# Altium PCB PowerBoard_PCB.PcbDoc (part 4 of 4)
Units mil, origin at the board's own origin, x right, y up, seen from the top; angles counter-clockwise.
Board outline 9251.97 x 3346.46 mil, 6 copper layers (Top Layer, Signal Layer 1, Signal Layer 2, Signal Layer 3, Signal Layer 4, Bottom Layer), stack 65.8 mil thick; 241 components, 145 nets, 894 pads, 120 vias.
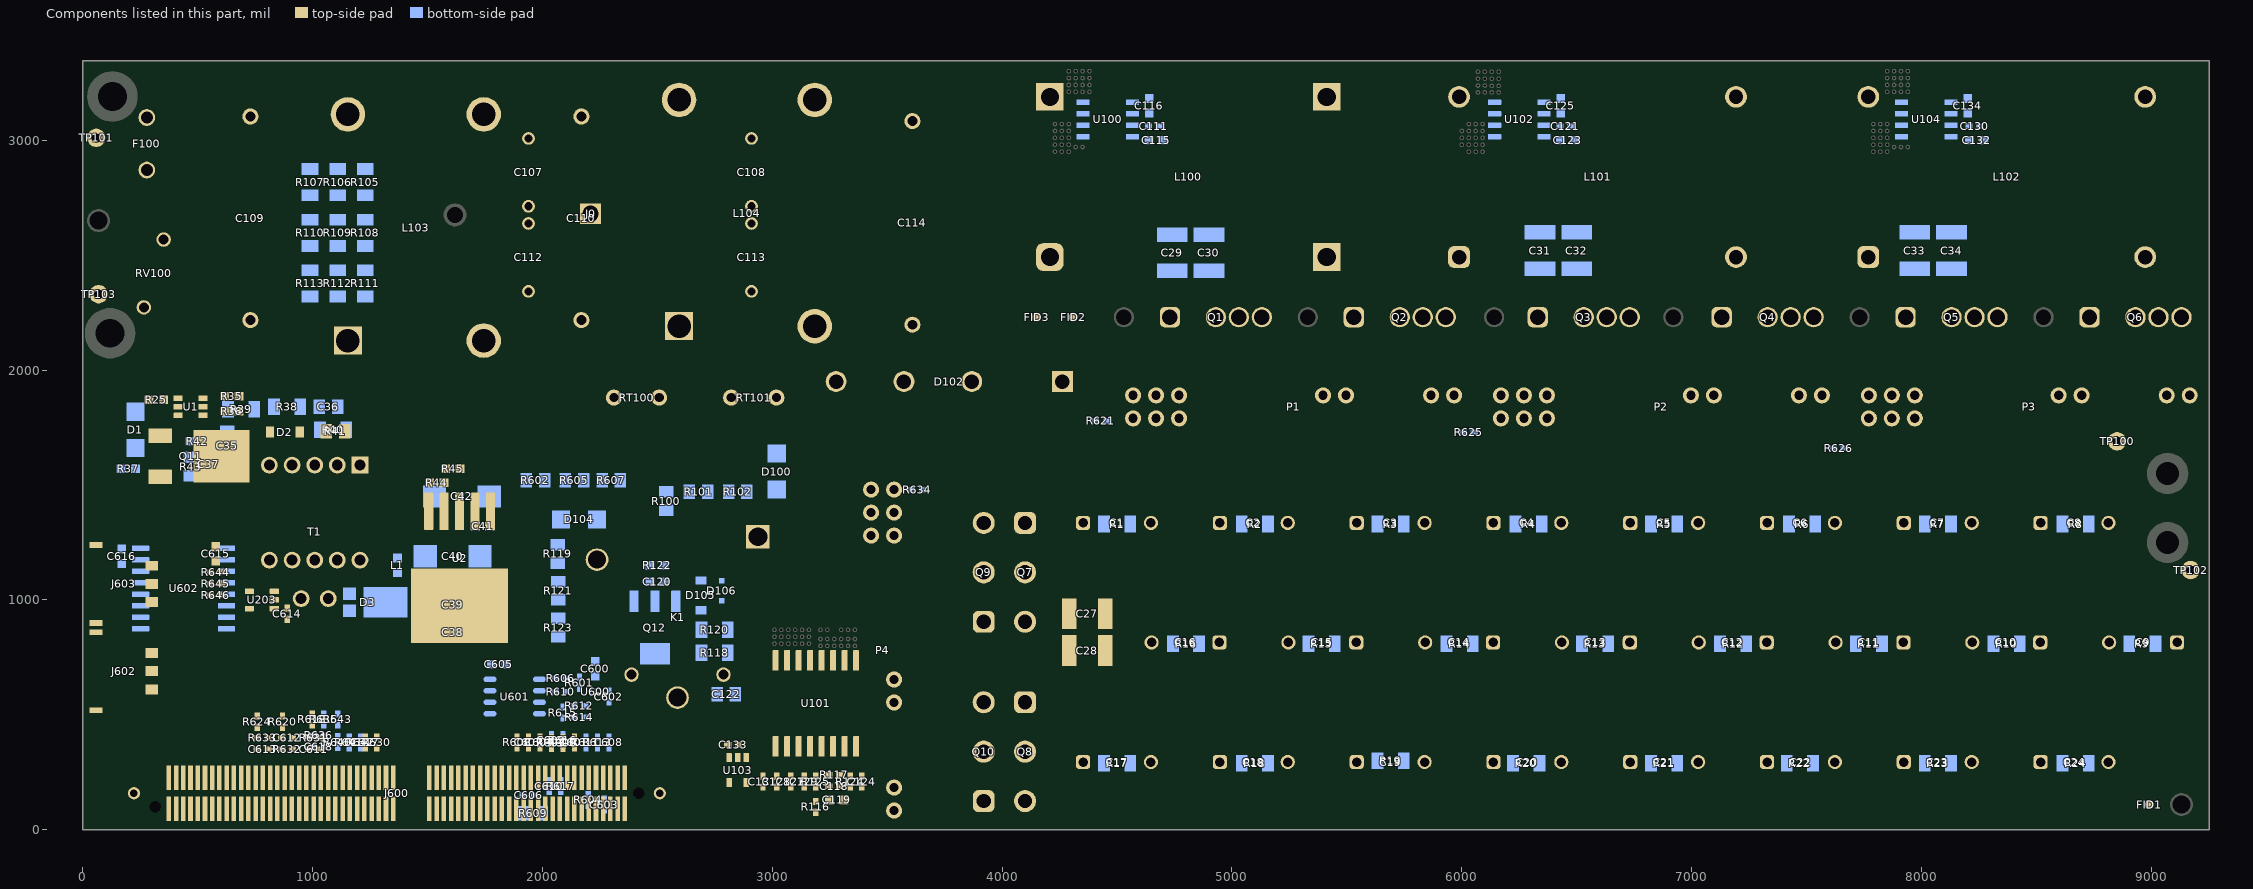
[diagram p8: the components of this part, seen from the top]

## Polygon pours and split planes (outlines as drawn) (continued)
NetC107_1 on Signal Layer 3 "Top Layer-No Net" (solid, pour order 398): 1580,3270 1630,3320 2700,3320 2750,3270 2750,3040 2700,2990 1630,2990 1580,3040
no net on Signal Layer 1 "Signal Layer 1-No Net 2" (solid, pour order 366): 3860,1170 3890,1200 4169.03,1200 4230,1260.97 4259.03,1260.97 4260,1260 4260,980 4230,980 4170,1040 3890,1040 3860,1070
NetC113_2 on Signal Layer 1 "Top Layer-No Net 8" (solid, remove dead copper, pour order 348): 3280,2300 3310,2270 3310,2250 3310,1250 3280,1220 2820,1220 2790,1250 2790,2260 2830,2300
AC_N on Signal Layer 1 "Signal Layer 1-No Net 5" (solid, pour order 342): 2170,1620 2490.13,1930.13 2855.07,1930.13 2871.7,1913.5 2871.7,1846.5 2855.07,1829.87 2656.06,1830 2630,1800 2620,1790 2620,1340 2780,1210 2170,1210
PFC_4H_S on Signal Layer 1 "Signal Layer 1-No Net 4" (solid, remove dead copper, pour order 340): 18 vertices, not listed, extent 3500,1399.92 4040,2000
AC_L on Signal Layer 1 "Signal Layer 1-No Net 3" (solid, remove dead copper, pour order 338): 3810,1900 3790,1920 3790,2040 3790,2890 4070,2890 4070,2090 4020,2030 4020,1920 4000,1900
NetL102_4 on Signal Layer 1 "Top Layer-No Net 4" (solid, remove dead copper, pour order 310): 17 vertices, not listed, extent 8080,2130 9040,2570
NetL101_4 on Signal Layer 1 "Top Layer-No Net 3" (solid, pour order 298): 6480,2190 6560,2110 7120,2110 7200,2190 7200,2310 7240,2350 7270,2380 7270,2550 7250,2570 6670,2570 6650,2550 6650,2410 6630,2390 6500,2390 6480,2370
NetL100_4 on Signal Layer 1 "Top Layer-No Net 9" (solid, pour order 288): 4880,2190 4960,2110 5510,2110 5600,2200 5600,2550 5580,2570 5110,2570 5080,2540 5080,2420 5049.92,2390 4900,2390 4880.08,2370
PFC_4H_S on Signal Layer 1 "Signal Layer 3-No Net" (solid, pour order 278): 17 vertices, not listed, extent 3190,230 4150,1440
NetC113_2 on Signal Layer 1 "Top Layer-No Net 6" (solid, pour order 256): 2830,2350 3600,2350 3650,2300 3650,2090 3600,2040 2850,2040 2790,2100 2790,2300
NetC110_2 on Signal Layer 1 "Top Layer-No Net" (solid, pour order 254): 1580,2300 1630,2350 2670,2350 2720,2300 2720,2050 2670,2000 1630,2000 1580,2050
NetC109_2 on Signal Layer 1 "Top Layer-No Net" (solid, pour order 244): 20,2300 70,2350 1280,2350 1330,2300 1330,2050 1280,2000 70,2000 20,2050
EARTH0 on Signal Layer 1 "Top Layer-No Net 11" (solid, pour order 230): 1560,2740 2940,2740 2970,2710 2970,2640 2940,2610 1560,2610 1530,2640 1530,2710
NetC109_1 on Signal Layer 1 "Top Layer-No Net" (solid, pour order 210): 200,3240 250,3280 1280,3280 1330,3240 1330,2870 1280,2820 250,2820 200,2880
NetF100_2 on Signal Layer 1 "Top Layer-No Net 1" (solid, pour order 200): 20,3290 50,3320 290,3320 340,3280 340,3070 310,3040 150,3040 120,3010 120,2990 100,2960 30,2960 20,2970
HVBUS on Signal Layer 1 "Signal Layer 1-No Net 2" (solid, pour order 158): 3860,1170 3890,1200 4169.03,1200 4230,1260.97 4259.03,1260.97 4260,1260 4260,980 4230,980 4170,1040 3890,1040 3860,1070
HVBUS on Signal Layer 1 "Signal Layer 1-No Net 1" (solid, pour order 154): 7990,2290 8020,2260 8020,2141.61 8120,2030 8120,2000 7730,2000 7730,2030 7840,2140 7840,2260 7870,2290
HVBUS on Signal Layer 1 "Signal Layer 1-No Net 1" (solid, pour order 152): 6390,2290 6420,2260 6420,2141.61 6520,2030 6520,2000 6130,2000 6130,2030 6240,2140 6240,2260 6270,2290
HVBUS on Signal Layer 1 "Signal Layer 1-No Net 1" (solid, pour order 150): 4790,2290 4820,2260 4820,2141.61 4920,2030 4920,2000 4530,2000 4530,2030 4640,2140 4640,2260 4670,2290
HVBUS on Signal Layer 1 "Signal Layer 1-No Net" (solid, pour order 148): 9160,2060 9230,2010 9230,490 8750,10 4270,10 4230,50 4230,2010 4277.17,2060
AC_L on Signal Layer 1 "Top Layer-No Net 5" (solid, pour order 138): 2820,3040 2820,3220 2860,3260 7920,3260 7960,3230 7960,2910 7880,2830 3230,2830 3180,2880 3140,2920 3080,2980 2880,2980
AC_N on Signal Layer 1 "Top Layer-No Net 7" (solid, pour order 120): 2200,1281.1 2710,1280 2770,1220 2840,1150 3130,1150 3180,1100 3180,610 3070,500 2350,500 2320,530 2320,730 2280,770 2200,770 2170,800 2170,1251.1
NetL102_2 on Signal Layer 1 "Bottom Layer-No Net" (solid, pour order 92): 7675,3250 7755,3330 7935,3330 7960,3305 7960,3115 7945,3100 7695,3100 7675,3120
NetL101_2 on Signal Layer 1 "Bottom Layer-No Net" (solid, pour order 66): 5905,3250 5985,3330 6165,3330 6190,3305 6190,3115 6175,3100 5925,3100 5905,3120
NetL100_2 on Signal Layer 1 "Bottom Layer-No Net" (solid, pour order 54): 4115,3250 4195,3330 4375,3330 4400,3305 4400,3115 4385,3100 4135,3100 4115,3120
NetC107_1 on Signal Layer 1 "Top Layer-No Net" (solid, pour order 382): 1580,3270 1630,3320 2700,3320 2750,3270 2750,3040 2700,2990 1630,2990 1580,3040
PGND on Signal Layer 4 "Signal Layer 3-No Net 2" (solid, remove dead copper, pour order 378): 4320,1770 4490,1940 8090,1940 8170,1860 8170,1167 8070,1067 3297,1067 2920,1444 2920,1770
PFC_4H_S on Signal Layer 4 "Signal Layer 3-No Net" (solid, pour order 376): 17 vertices, not listed, extent 3190,230 4150,1400
HVBUS on Signal Layer 4 "Signal Layer 4-No Net" (solid, remove dead copper, pour order 372): 4490,1040 4530,1080 4530,1380 4500,1410 4280,1410 4243.21,1373.21 4240,1373.21 4240,1270.08 4169.92,1200 4224.01,1200 3890,1200 3860,1170 3860,1070 3890,1040
PGND on Signal Layer 4 "Signal Layer 3-No Net 1" (solid, remove dead copper, pour order 314): 22 vertices, not listed, extent 480,10 3460,1770
NetL102_4 on Signal Layer 4 "Top Layer-No Net 4" (solid, remove dead copper, pour order 304): 17 vertices, not listed, extent 8080,2130 9040,2570
NetL102_4 on Signal Layer 4 "Top Layer-No Net 4" (solid, remove dead copper, pour order 306): 17 vertices, not listed, extent 8080,2130 9040,2570
NetL101_4 on Signal Layer 4 "Top Layer-No Net 3" (solid, pour order 292): 6480,2190 6560,2110 7120,2110 7200,2190 7200,2310 7240,2350 7270,2380 7270,2550 7250,2570 6670,2570 6650,2550 6650,2410 6630,2390 6500,2390 6480,2370
NetL101_4 on Signal Layer 4 "Top Layer-No Net 3" (solid, pour order 294): 6480,2190 6560,2110 7120,2110 7200,2190 7200,2310 7240,2350 7270,2380 7270,2550 7250,2570 6670,2570 6650,2550 6650,2410 6630,2390 6500,2390 6480,2370
NetL100_4 on Signal Layer 4 "Top Layer-No Net 9" (solid, remove dead copper, pour order 284): 4880,2190 4960,2110 5510,2110 5600,2200 5600,2550 5580,2570 5110,2570 5080,2540 5080,2420 5049.92,2390 4900,2390 4880.08,2370
NetC110_2 on Signal Layer 4 "Top Layer-No Net" (solid, pour order 246): 1580,2300 1630,2350 2670,2350 2720,2300 2720,2050 2670,2000 1630,2000 1580,2050
NetC109_2 on Signal Layer 4 "Top Layer-No Net" (solid, pour order 238): 20,2300 70,2350 1280,2350 1330,2300 1330,2050 1280,2000 70,2000 20,2050
NetC109_2 on Signal Layer 4 "Top Layer-No Net" (solid, pour order 240): 20,2300 70,2350 1280,2350 1330,2300 1330,2050 1280,2000 70,2000 20,2050
EARTH0 on Signal Layer 4 "Top Layer-No Net 11" (solid, pour order 226): 1560,2740 2940,2740 2970,2710 2970,2640 2940,2610 1560,2610 1530,2640 1530,2710
NetC109_1 on Signal Layer 4 "Top Layer-No Net" (solid, pour order 204): 200,3240 250,3280 1280,3280 1330,3240 1330,2870 1280,2820 250,2820 200,2880
NetC109_1 on Signal Layer 4 "Top Layer-No Net" (solid, pour order 206): 200,3240 250,3280 1280,3280 1330,3240 1330,2870 1280,2820 250,2820 200,2880
NetF100_2 on Signal Layer 4 "Top Layer-No Net 1" (solid, pour order 196): 20,3290 50,3320 290,3320 340,3280 340,3070 310,3040 150,3040 120,3010 120,2990 100,2960 30,2960 20,2970
AC_L on Signal Layer 4 "Top Layer-No Net 5" (solid, pour order 134): 2820,3040 2820,3220 2860,3260 7920,3260 7960,3230 7960,2910 7880,2830 3230,2830 3180,2880 3140,2920 3080,2980 2880,2980
NetL102_2 on Signal Layer 4 "Bottom Layer-No Net" (solid, pour order 96): 7675,3250 7755,3330 7935,3330 7960,3305 7960,3115 7945,3100 7695,3100 7675,3120
NetL101_2 on Signal Layer 4 "Bottom Layer-No Net" (solid, pour order 70): 5905,3250 5985,3330 6165,3330 6190,3305 6190,3115 6175,3100 5925,3100 5905,3120
NetL100_2 on Signal Layer 4 "Bottom Layer-No Net" (solid, pour order 60): 4115,3250 4195,3330 4375,3330 4400,3305 4400,3115 4385,3100 4135,3100 4115,3120
NetC107_1 on Signal Layer 4 "Top Layer-No Net" (solid, pour order 396): 1580,3270 1630,3320 2700,3320 2750,3270 2750,3040 2700,2990 1630,2990 1580,3040
PFC_4H_S on Signal Layer 2 "Signal Layer 3-No Net" (solid, remove dead copper, pour order 362): 17 vertices, not listed, extent 3190,230 4150,1440
HVBUS on Signal Layer 2 "Signal Layer 1-No Net 2" (solid, pour order 360): 3860,1170 3890,1200 4169.03,1200 4230,1260.97 4259.03,1260.97 4260,1260 4260,980 4230,980 4170,1040 3890,1040 3860,1070
AC_L on Signal Layer 2 "Signal Layer 1-No Net 3" (solid, remove dead copper, pour order 352): 3810,1900 3790,1920 3790,2040 3790,2890 4070,2890 4070,2090 4020,2030 4020,1920 4000,1900 4020,1920 4000,1900
PFC_4H_S on Signal Layer 2 "Signal Layer 1-No Net 4" (solid, remove dead copper, pour order 350): 18 vertices, not listed, extent 3500,1399.92 4040,2000
NetC113_2 on Signal Layer 2 "Top Layer-No Net 8" (solid, remove dead copper, pour order 346): 3280,2300 3310,2270 3310,2250 3310,1250 3280,1220 2820,1220 2790,1250 2790,2260 2830,2300
AC_N on Signal Layer 2 "Signal Layer 1-No Net 5" (solid, remove dead copper, pour order 344): 2170,1620 2490.13,1930.13 2855.07,1930.13 2871.7,1913.5 2871.7,1846.5 2855.07,1829.87 2656.06,1830 2630,1800 2620,1790 2620,1340 2780,1210 2170,1210
NetL102_4 on Signal Layer 2 "Top Layer-No Net 4" (solid, remove dead copper, pour order 302): 17 vertices, not listed, extent 8080,2130 9040,2570
NetL101_4 on Signal Layer 2 "Top Layer-No Net 3" (solid, pour order 290): 6480,2190 6560,2110 7120,2110 7200,2190 7200,2310 7240,2350 7270,2380 7270,2550 7250,2570 6670,2570 6650,2550 6650,2410 6630,2390 6500,2390 6480,2370
NetL100_4 on Signal Layer 2 "Top Layer-No Net 9" (solid, remove dead copper, pour order 282): 4880,2190 4960,2110 5510,2110 5600,2200 5600,2550 5580,2570 5110,2570 5080,2540 5080,2420 5049.92,2390 4900,2390 4880.08,2370
HVBUS on Signal Layer 2 "Signal Layer 1-No Net 1" (solid, pour order 274): 7990,2290 8020,2260 8020,2141.61 8120,2030 8120,2000 7730,2000 7730,2030 7840,2140 7840,2260 7870,2290
HVBUS on Signal Layer 2 "Signal Layer 1-No Net 1" (solid, pour order 272): 6390,2290 6420,2260 6420,2141.61 6520,2030 6520,2000 6130,2000 6130,2030 6240,2140 6240,2260 6270,2290
HVBUS on Signal Layer 2 "Signal Layer 1-No Net 1" (solid, pour order 270): 4790,2290 4820,2260 4820,2141.61 4920,2030 4920,2000 4530,2000 4530,2030 4640,2140 4640,2260 4670,2290
HVBUS on Signal Layer 2 "Signal Layer 1-No Net" (solid, pour order 260): 9160,2060 9230,2010 9230,490 8750,10 4270,10 4230,50 4230,2010 4277.17,2060
NetC113_2 on Signal Layer 2 "Top Layer-No Net 6" (solid, pour order 258): 2830,2350 3600,2350 3650,2300 3650,2090 3600,2040 2850,2040 2790,2100 2790,2300
NetC110_2 on Signal Layer 2 "Top Layer-No Net" (solid, pour order 250): 1580,2300 1630,2350 2670,2350 2720,2300 2720,2050 2670,2000 1630,2000 1580,2050
NetC109_2 on Signal Layer 2 "Top Layer-No Net" (solid, pour order 236): 20,2300 70,2350 1280,2350 1330,2300 1330,2050 1280,2000 70,2000 20,2050
EARTH0 on Signal Layer 2 "Top Layer-No Net 11" (solid, pour order 224): 1560,2740 2940,2740 2970,2710 2970,2640 2940,2610 1560,2610 1530,2640 1530,2710
NetC109_1 on Signal Layer 2 "Top Layer-No Net" (solid, pour order 202): 200,3240 250,3280 1280,3280 1330,3240 1330,2870 1280,2820 250,2820 200,2880
NetF100_2 on Signal Layer 2 "Top Layer-No Net 1" (solid, pour order 194): 20,3290 50,3320 290,3320 340,3280 340,3070 310,3040 150,3040 120,3010 120,2990 100,2960 30,2960 20,2970
AC_L on Signal Layer 2 "Top Layer-No Net 5" (solid, pour order 132): 2820,3040 2820,3220 2860,3260 7920,3260 7960,3230 7960,2910 7880,2830 3230,2830 3180,2880 3140,2920 3080,2980 2880,2980
AC_N on Signal Layer 2 "Top Layer-No Net 7" (solid, pour order 118): 2200,1281.1 2710,1280 2770,1220 2840,1150 3130,1150 3180,1100 3180,610 3070,500 2350,500 2320,530 2320,730 2280,770 2200,770 2170,800 2170,1251.1
NetL102_2 on Signal Layer 2 "Bottom Layer-No Net" (solid, pour order 98): 7675,3250 7755,3330 7935,3330 7960,3305 7960,3115 7945,3100 7695,3100 7675,3120
NetL101_2 on Signal Layer 2 "Bottom Layer-No Net" (solid, pour order 72): 5905,3250 5985,3330 6165,3330 6190,3305 6190,3115 6175,3100 5925,3100 5905,3120
NetL100_2 on Signal Layer 2 "Bottom Layer-No Net" (solid, pour order 62): 4115,3250 4195,3330 4375,3330 4400,3305 4400,3115 4385,3100 4135,3100 4115,3120
NetC107_1 on Signal Layer 2 "Top Layer-No Net" (solid, pour order 400): 1580,3270 1630,3320 2700,3320 2750,3270 2750,3040 2700,2990 1630,2990 1580,3040

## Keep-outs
Keep-Out Layer:
  lines w10: 0,0 0,3346.46 9251.97,3346.46 9251.97,0 0,0 ; 100,1300 100,1360 450,1360 450,400 160,400 160,460 390,460 390,1300 100,1300
  text ".Layer_Name" at 577,-858.49 h60

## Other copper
Top Layer:
  text ".Layer_Name" at 577,-858.49 h60
Bottom Layer:
  text ".Layer_Name" at 577,-858.49 h60

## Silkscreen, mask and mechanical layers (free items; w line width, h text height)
Top Overlay:
  lines w5: 490,833.46 610,833.46 ; 490,980 610,980 ; 510,980 529.5,999.5 ; 720,410 690,410 650,450 650,610 695,655 730,655 ; 1920,515 1935,515 2010,440 ; 2900,155 2900,156.38 2930,186.38 ; 730,550 1110,550 1110,760 730,760 730,550 ; 1670,450 1670,580 1920,580 1920,450 1670,450 ; 2730,20 3150,20 3150,155 2730,155 2730,20
  lines w10: 3930,2340 3930,3340 5690,3340 5690,2340 3930,2340 ; 5710,2340 7470,2340 7470,3340 5710,3340 5710,2340 ; 7490,2340 9250,2340 9250,3340 7490,3340 7490,2340
  text "AC_L" at 220,3300 h40
  text "AC_N" at 60,2000 h40
  text "TIDA-01604" at 1200,1910 h48
  text "EDGE #: 6614192A" at 1210,1840 h48
  text "6.6kW Totem-Pole PFC" at 1210,1770 h48
  text "DC+" at 9110,1690 h40
  text "DC-" at 9110,1350 h40
  text ".Layer_Name" at 577,-858.49 h60
Bottom Overlay:
  lines w5: 760,2930 760,2970 830,3040 1070,3040 1130,2980 1130,2930 ; 660,2280 880,2280 880,2300 880,2930 660,2930 660,2280 ; 990,540 1260,540 1260,670 1180,670 1180,800 1060,800 1060,660 990,660 990,540
  text ".Layer_Name" at 577,-858.49 h60
Top Paste:
  text ".Layer_Name" at 577,-858.49 h60
Bottom Paste:
  text ".Layer_Name" at 577,-858.49 h60
Top Solder:
  text ".Layer_Name" at 577,-858.49 h60
  text ".Layer_Name" at 577,-858.49 h60
Bottom Solder:
  text ".Layer_Name" at 577,-858.49 h60
Drill Guide:
  text ".Layer_Name" at 577,-858.49 h60
M1 Board Outline:
  text ".Layer_Name" at 577,-858.49 h60
M2 Board Dimensions:
  rectangle: 0,-275 125,-150
  rectangle: 125,-400 500,-275
  lines w7: 0,-275 1000,-275 ; 125,-400 125,-150 ; 250,-400 250,-150 ; 500,-400 500,-150 ; 750,-400 750,-150 ; 0,-400 1000,-400 1000,-150 0,-150 0,-400
  lines w10: -6.58,-1.82 9245.39,-1.82 ; 0,0 0,3346.46 9251.97,3346.46 9251.97,0
  text ".Layer_Name" at 577,-858.49 h60
M3 3D STEP Top:
  text ".Layer_Name" at 577,-858.49 h60
M4 3D STEP Bottom:
  text ".Layer_Name" at 577,-858.49 h60
M5 Assembly Top:
  lines w10: -292,-930.17 6308,-930.17 ; -292,-726.83 6310,-726.83 ; -292,-523.5 -292,-1133.5 3713,-1133.5 6310,-1133.5 6310,-523.5 -291.5,-523.5 -291.5,-1133.5 1284,-1133.5 ; 2173,-1133.5 2173,-523.5 ; 3440,-726.83 3440,-523.5 ; 4280,-726.83 4280,-523.5 ; 4902,-1140 4902,-937.17
  text "COMPONENTS MARKED 'DNP' SHOULD NOT BE POPULATED." at 1153.5,-318.5 h60
  text "ASSEMBLY VARIANT:" at 1153,-434 h60
  text ".VariantName" at 2189,-434 h60
  text "PCB VIEWED FROM TOP SIDE" at -228.5,-655.67 h60
  text "BOARD #:" at 2248,-655.67 h60
  text ".PRJ_Number" at 2793.5,-655.67 h60
  text "REV:" at 3638,-655.67 h60
  text ".PCB_Rev" at 3929.5,-655.67 h60
  text "SVN REV:" at 4476,-655.67 h60
  text ".VersionControl_RevNumber" at 4982,-655.67 h60
  text "TID #:" at 2248,-859 h60
  text ".TID" at 2793.5,-859 h60
  text "PLOT NAME =" at -228.5,-1064.34 h60
  text ".plot_File_Name" at 577,-1064.34 h60
  text "GENERATED    :" at 2250,-1064.34 h60
  text ".Print_Date" at 3119.5,-1064.34 h60
  text ".Print_Time" at 3848.5,-1064.34 h60
  text "TEXAS INSTRUMENTS" at 5113,-1064.34 h60
M6 Assembly Bottom:
  lines w10: -292.5,-727.33 6309.5,-727.33 ; -290.5,-930.67 6309.5,-930.67 ; 1115.5,-1140.5 1115.5,-937.67 ; 1737.5,-727.33 1737.5,-524 ; 2577.5,-727.33 2577.5,-524 ; 3844.5,-1134 3844.5,-524 ; 4733.5,-1134 6309,-1134 6309,-524 -292.5,-524 -292.5,-1134 2304.5,-1134 6309.5,-1134 6309.5,-524
  text "COMPONENTS MARKED 'DNP' SHOULD NOT BE POPULATED." at 6102,-318 h60
  text ".VersionControl_RevNumber" at 1035.5,-656.17 h60
  text "SVN REV:" at 1541.5,-656.17 h60
  text ".PCB_Rev" at 2088,-656.17 h60
  text "REV:" at 2379.5,-656.17 h60
  text ".PRJ_Number" at 3224,-656.17 h60
  text "BOARD #:" at 3769.5,-656.17 h60
  text "PCB VIEWED FROM BOTTOM SIDE" at 6246,-656.17 h60
  text ".TID" at 3224,-859.5 h60
  text "TID #:" at 3769.5,-859.5 h60
  text "TEXAS INSTRUMENTS" at 904.5,-1064.84 h60
  text ".Print_Time" at 2169,-1064.84 h60
  text ".Print_Date" at 2898,-1064.84 h60
  text "GENERATED    :" at 3767.5,-1064.84 h60
  text ".plot_File_Name" at 5440.5,-1064.84 h60
  text "PLOT NAME =" at 6246,-1064.84 h60
M9 Title Sheet:
  drawing of 57 lines, arcs and shapes, not listed
  text "1" at 739.84,8036.5 h70
  text "2" at 3235.5,8036.5 h70
  text "3" at 5724.84,8036.5 h70
  text "4" at 8231.51,8036.5 h70
  text "5" at 10730.5,8036.5 h70
  text "6" at 13235.5,8036.5 h70
  text "A" at -416.5,6893.5 h70
  text "A" at 14383.5,6893.5 h70
  text "B" at -416.5,4513.5 h70
  text "B" at 14383.5,4513.5 h70
  text "C" at -416.5,2138.5 h70
  text "C" at 14383.5,2138.5 h70
  text "PROJECT TITLE:" at 11343.5,277.5 h45
  text ".PRJ_Title" at 11393.5,144.17 h70
  text "DESIGNED FOR:" at 11343.5,-23.5 h45
  text ".PRJ_Customer" at 11393.5,-163.5 h70
  text "D" at -416.5,-231.5 h70
  text "D" at 14383.5,-231.5 h70
  text "FILE NAME:" at 11343.5,-323.5 h45
  text ".PCB_File_Name_No_Path" at 11393.5,-443.5 h70
  text "Texas Instruments (TI) and/or its licensors do not warrant the accuracy or completeness of this specification" at 6374,-605.34 h45
  text "ENGINEER:" at 11343.5,-613.5 h45
  text "LAYOUT BY:" at 12848.5,-613.5 h45
  text "or any information contained therein. TI and/or its licensors do not warrant that this design will meet" at 6329.01,-718 h45
  text ".PRJ_Engineer" at 11393.5,-768.49 h70
  text ".PCB_Layout" at 12899,-768.49 h70
  text "the specifications, will be suitable for your application or fit for any particular purpose, or will operate in" at 6329.01,-830.67 h45
  text ".Layer_Name" at 577,-858.49 h60
  text "ALTIUM DESIGNER VERSION:" at 12848.5,-923.5 h45
  text "an implementation. TI and/or its licensors do not warrant that the design is production worthy. You should" at 6329.01,-943.33 h45
  text "completely validate and test your design implementation to confirm the system functionality for your application." at 6374,-1056 h45
  text ".print_Scale" at 11393.5,-1056.83 h70
  text ".Application_BuildNumber" at 12899,-1056.83 h70
  text "1" at 739.84,-1263.5 h70
  text "2" at 3235.5,-1263.5 h70
  text "3" at 5724.84,-1263.5 h70
  text "4" at 8231.51,-1263.5 h70
  text "5" at 10730.5,-1263.5 h70
  text "6" at 13235.5,-1263.5 h70
M10 Fab Notes:
  drawing of 173 lines, arcs and shapes, not listed
  text "DESIGN INFORMATION" at 12378.02,6201 h60
  text "MIN. TRACK WIDTH:" at 11733.46,6021 h60
  text "7" at 12829.7,6021 h60
  text "MIL" at 12984.46,6021 h60
  text "MIN. CLEARANCE:" at 11733.46,5889 h60
  text "0.2" at 12769.7,5889 h60
  text "mm" at 12984.46,5889 h60
  text "MIN. VIA PAD SIZE:" at 11733.46,5757 h60
  text "10" at 12799.71,5757 h60
  text "MIL" at 12984.46,5757 h60
  text "0.05mm (2MIL)" at 12428.46,5615.29 h60
  text "MINIMUM ANNULAR RING" at 11404.23,5611 h60
  text "EXTERNAL" at 13136.46,5611 h60
  text "PER" at 11604.23,5493 h60
  text "IPC-D-275 CLASS 2 LEVEL C" at 11824.23,5493 h60
  text "MIL, HOLES" at 13312.46,5380.71 h60
  text "+/-" at 12920,5380 h60
  text "+/-" at 13774,5380 h60
  text "REGISTRATION TOLERANCES:" at 11404.23,5375 h60
  text "METAL" at 12604,5375 h60
  text "5" at 13180.2,5375 h60
  text "3" at 14013.2,5375 h60
  text "MIL" at 14129.46,5375 h60
  text "+/-" at 13774,5262 h60
  text "HOLE SIZE TOLERANCE (UNLESS OTHERWISE SPECIFIED):" at 11404.23,5257 h60
  text "3" at 14013.2,5257 h60
  text "MIL" at 14129.46,5257 h60
  text "MATERIAL:" at 11329.46,5047.54 h60
  text "FR-4 High Tg" at 12315.9,4907.21 h60
  text "FR-408" at 11750.46,4898.64 h60
  text "OTHER" at 13238.46,4898.64 h60
  text "X" at 12161,4895 h60
  text "62 MIL (1.6mm) +/-10%" at 12070.56,4735.92 h60
  text "THICKNESS:" at 11404.23,4731.64 h60
  text "X" at 11942.4,4731.64 h60
  text "OTHER" at 13355.46,4731.64 h60
  text "TOLERANCE:" at 11404.23,4573.64 h60
  text "X" at 12243.53,4573.64 h60
  text "ANSI IPC-6012 TYPE 3 CLASS 2" at 12430.48,4573.64 h60
  text "OTHER +/-" at 12430.46,4417.64 h60
  text "BOW & TWIST:" at 11404.23,4260.64 h60
  text "X" at 12243.53,4260.64 h60
  text "ANSI IPC-6012 TYPE 3 CLASS 2" at 12430.48,4260.64 h60
  text "OTHER +/-" at 12430.46,4102.13 h60
  text "DRILLING:" at 11329.46,3963.64 h60
  text "REFERENCE:" at 11404.23,3846.64 h60
  text "X" at 12052.46,3846.64 h60
  text "AS SHOWN" at 12239.46,3846.64 h60
  text "X" at 12953.46,3846.64 h60
  text "NC_DRILL FILES" at 13090.46,3846.64 h60
  text "PTH COPPER THICKNESS:" at 11404.23,3688.64 h60
  text "X" at 12534.46,3688.64 h60
  text "20-30 um" at 12671.46,3688.64 h60
  text "OTHER" at 13388.46,3688.64 h60
  text "BOARD FINISH:" at 11329.46,3529.64 h60
  text "SILKSCREEN:" at 11484.68,3411.64 h60
  text "X" at 12433.46,3411.64 h60
  text "TOP" at 12559.46,3411.64 h60
  text "X" at 12943.46,3411.64 h60
  text "BOTTOM" at 13070.46,3411.64 h60
  text "SILKSCREEN COLOR:" at 11484.68,3244.64 h60
  text "X" at 12432.42,3244.64 h60
  text "WHITE" at 12559.46,3244.64 h60
  text "OTHER" at 13070.46,3244.64 h60
  text "X" at 12563.42,3085.44 h60
  text "GREEN" at 12690.46,3085.44 h60
  text "OTHER" at 13308.46,3085.44 h60
  text "SOLDER RESIST COLOR:" at 11484.68,3074.64 h60
  text "X" at 12563.42,2915.44 h60
  text "MATTE" at 12690.46,2915.44 h60
  text "SEMI-GLOSS" at 13308,2914.8 h60
  text "IMMERSION GOLD (ENIG)" at 12390.46,2726.92 h60
  text "ENEPIG" at 13728,2723.64 h60
  text "SURFACE FINISH:" at 11329.46,2722.64 h60
  text "IMM. TIN/SILVER OR EQUIV" at 11659,2565.64 h60
  text "OTHER" at 13090.46,2565.64 h60
  text "X" at 11500,2560 h60
  text "ARRAY/PANEL:" at 11329.46,2386.64 h60
  text "CUT AND TRIM PER M1 BOARD OUTLINE" at 12390.46,2382.35 h60
  text "N.C. ROUTE" at 12390.46,2230.64 h60
  text "X" at 13069.46,2230.64 h60
  text "V. SCORE" at 13256.46,2230.64 h60
  text "CERTIFICATION:" at 11329.46,2093.64 h60
  text "MATERIALS AND WORKMANSHIP FOR ALL PCBS" at 12054.46,2093.64 h60
  text "TO MEET OR EXCEED THE REQUIREMENTS OF:" at 12054.46,1995.64 h60
  text "X" at 11680.96,1859.13 h60
  text "ANSI IPC-A-600F CLASS ->" at 11819.96,1859.13 h60
  text "X" at 13459.02,1859.13 h60
  text "2" at 13577.96,1859.14 h60
  text "1" at 13262.96,1857.64 h60
  text "3" at 13931.96,1857.64 h60
  text "X" at 12495.02,1699.64 h60
  text "RoHS" at 12631.96,1699.64 h60
  text "OTHER" at 13276.36,1699.64 h60
  text "PER ORDER" at 13673.42,1699.64 h60
  text "ALL BOARDS MUST MEET OR EXCEED UL94-V0 REQUIREMENTS." at 11357,1534 h60
  text "PCB MUST BEAR THE UL94V-0 UL REGISTERED MATERIAL ID NUMBER" at 11357,1414 h60
  text "ADDITIONAL REQUIREMENTS:" at 11329.46,1240.64 h60
  text "MICROSECTION:" at 11404.23,1125.64 h60
  text "YES" at 12309.96,1125.64 h60
  text "REQUIRED" at 13171.46,969.49 h60
  text "BARE BOARD ELEC. TEST:" at 11404.23,966.64 h60
  text "NONE" at 12709.96,966.64 h60
  text "X" at 13044.46,966.64 h60
  text "PER ORDER" at 13763.46,966.64 h60
  text ".Layer_Name" at 577,-858.49 h60
M11 Gerber Information:
  lines w10: -292,-930.17 6308,-930.17 ; -292,-726.83 6310,-726.83 ; -292,-523.5 -292,-1133.5 3713,-1133.5 6310,-1133.5 6310,-523.5 -291.5,-523.5 -291.5,-1133.5 1284,-1133.5 ; 2173,-1133.5 2173,-523.5 ; 3440,-726.83 3440,-523.5 ; 4280,-726.83 4280,-523.5 ; 4902,-1140 4902,-937.17
  text "ALL ARTWORK VIEWED FROM TOP SIDE" at -228.5,-655.67 h60
  text "BOARD #:" at 2248,-655.67 h60
  text ".PRJ_Number" at 2793.5,-655.67 h60
  text "REV:" at 3638,-655.67 h60
  text ".PCB_Rev" at 3929.5,-655.67 h60
  text "SVN REV:" at 4476,-655.67 h60
  text ".VersionControl_RevNumber" at 4982,-655.67 h60
  text "LAYER NAME =" at -228.5,-858.49 h60
  text "TID #:" at 2248,-859 h60
  text ".TID" at 2793.5,-859 h60
  text "PLOT NAME =" at -228.5,-1064.34 h60
  text ".plot_File_Name" at 577,-1064.34 h60
  text "GENERATED    :" at 2250,-1064.34 h60
  text ".Print_Date" at 3119.5,-1064.34 h60
  text ".Print_Time" at 3848.5,-1064.34 h60
  text "TEXAS INSTRUMENTS" at 5113,-1064.34 h60
M12 Stackup:
  drawing of 399 lines, arcs and shapes, not listed
  text "Layer" at 3260.58,7760 h60
  text "Name" at 3670.49,7760 h60
  text "Material" at 4610.23,7760 h60
  text "Thickness" at 5470,7760 h60
  text "Constant" at 6119.84,7760 h60
  text "Board Layer Stack" at 6689.7,7760 h60
  text "1" at 3260.58,7640 h60
  text "Top Overlay" at 3670.49,7640 h60
  text "2" at 3260.58,7520 h60
  text "Top Solder" at 3670.49,7520 h60
  text "Solder Resist" at 4610.23,7520 h60
  text "0.40mil" at 5470,7520 h60
  text "3.5" at 6119.84,7520 h60
  text "3" at 3260.58,7400 h60
  text "Top Layer" at 3670.49,7400 h60
  text "Copper" at 4610.23,7400 h60
  text "2.80mil" at 5470,7400 h60
  text "4" at 3260.58,7280 h60
  text "Dielectric1" at 3670.49,7280 h60
  text "7.00mil" at 5470,7280 h60
  text "4.2" at 6119.84,7280 h60
  text "5" at 3260.58,7160 h60
  text "Signal Layer 1" at 3670.49,7160 h60
  text "Copper" at 4610.23,7160 h60
  text "2.80mil" at 5470,7160 h60
  text "6" at 3260.58,7040 h60
  text "Dielectric 3" at 3670.49,7040 h60
  text "FR-4" at 4610.23,7040 h60
  text "14.00mil" at 5470,7040 h60
  text "4.2" at 6119.84,7040 h60
  text "7" at 3260.58,6920 h60
  text "Signal Layer 2" at 3670.49,6920 h60
  text "Copper" at 4610.23,6920 h60
  text "2.80mil" at 5470,6920 h60
  text "8" at 3260.58,6800 h60
  text "Dielectric 2" at 3670.49,6800 h60
  text "7.00mil" at 5470,6800 h60
  text "4.2" at 6119.84,6800 h60
  text "9" at 3260.58,6680 h60
  text "Signal Layer 3" at 3670.49,6680 h60
  text "Copper" at 4610.23,6680 h60
  text "2.80mil" at 5470,6680 h60
  text "10" at 3260.58,6560 h60
  text "Dielectric 4" at 3670.49,6560 h60
  text "7.00mil" at 5470,6560 h60
  text "4.2" at 6119.84,6560 h60
  text "11" at 3260.58,6440 h60
  text "Signal Layer 4" at 3670.49,6440 h60
  text "Copper" at 4610.23,6440 h60
  text "2.80mil" at 5470,6440 h60
  text "12" at 3260.58,6320 h60
  text "Dielectric 5" at 3670.49,6320 h60
  text "FR-4" at 4610.23,6320 h60
  text "14.00mil" at 5470,6320 h60
  text "4.2" at 6119.84,6320 h60
  text "13" at 3260.58,6200 h60
  text "Bottom Layer" at 3670.49,6200 h60
  text "Copper" at 4610.23,6200 h60
  text "2.80mil" at 5470,6200 h60
  text "14" at 3260.58,6080 h60
  text "Bottom Solder" at 3670.49,6080 h60
  text "Solder Resist" at 4610.23,6080 h60
  text "0.40mil" at 5470,6080 h60
  text "3.5" at 6119.84,6080 h60
  text "15" at 3260.58,5960 h60
  text "Bottom Overlay" at 3670.49,5960 h60
  text ".Layer_Name" at 577,-858.49 h60
M13 Component Bodies Top:
  text ".Layer_Name" at 577,-858.49 h60
M14 Component Bodies Bottom:
  text ".Layer_Name" at 577,-858.49 h60
M15 Courtyards Top:
  text ".Layer_Name" at 577,-858.49 h60
M16 Courtyards Bottom:
  text ".Layer_Name" at 577,-858.49 h60
Drill Drawing:
  drawing of 168 lines, arcs and shapes, not listed
  text "Symbol" at -189.41,7852.98 h72
  text "Quantity" at 111.16,7852.98 h72
  text "Finished Hole Size" at 443.16,7852.98 h72
  text "Plated" at 1079.72,7852.98 h72
  text "Hole Type" at 1338.86,7852.98 h72
  text "Drill Layer Pair" at 1714.02,7852.98 h72
  text "Tolerance" at 2438.35,7852.98 h72
  text "2" at 111.16,7728.66 h60
  text "1.270mm (50.00mil)" at 443.16,7728.66 h60
  text "NPTH" at 1079.72,7728.66 h60
  text "Round" at 1338.86,7728.66 h60
  text "Top Layer - Bottom Layer" at 1714.02,7728.66 h60
  text "D" at -214.69,7718.67 h55.25
  text "252" at 111.16,7604.34 h60
  text "0.254mm (10.00mil)" at 443.16,7604.34 h60
  text "PTH" at 1079.72,7604.34 h60
  text "Round" at 1338.86,7604.34 h60
  text "Top Layer - Bottom Layer" at 1714.02,7604.34 h60
  text "I" at -205.49,7594.34 h55.25
  text "3" at 111.16,7480.02 h60
  text "0.508mm (20.00mil)" at 443.16,7480.02 h60
  text "PTH" at 1079.72,7480.02 h60
  text "Round" at 1338.86,7480.02 h60
  text "Top Layer - Bottom Layer" at 1714.02,7480.02 h60
  text "1" at 111.16,7355.7 h60
  text "0.762mm (30.00mil)" at 443.16,7355.7 h60
  text "PTH" at 1079.72,7355.7 h60
  text "Round" at 1338.86,7355.7 h60
  text "Top Layer - Bottom Layer" at 1714.02,7355.7 h60
  text "2" at 111.16,7231.38 h60
  text "0.840mm (33.07mil)" at 443.16,7231.38 h60
  text "PTH" at 1079.72,7231.38 h60
  text "Round" at 1338.86,7231.38 h60
  text "Top Layer - Bottom Layer" at 1714.02,7231.38 h60
  text "C" at -214.69,7221.39 h55.25
  text "8" at 111.16,7107.06 h60
  text "0.900mm (35.43mil)" at 443.16,7107.06 h60
  text "PTH" at 1079.72,7107.06 h60
  text "Round" at 1338.86,7107.06 h60
  text "Top Layer - Bottom Layer" at 1714.02,7107.06 h60
  text "48" at 111.16,6982.74 h60
  text "1.016mm (40.00mil)" at 443.16,6982.74 h60
  text "PTH" at 1079.72,6982.74 h60
  text "Round" at 1338.86,6982.74 h60
  text "Top Layer - Bottom Layer" at 1714.02,6982.74 h60
  text "48" at 111.16,6858.42 h60
  text "1.050mm (41.34mil)" at 443.16,6858.42 h60
  text "PTH" at 1079.72,6858.42 h60
  text "Round" at 1338.86,6858.42 h60
  text "Top Layer - Bottom Layer" at 1714.02,6858.42 h60
  text "2" at 111.16,6734.1 h60
  text "1.090mm (42.91mil)" at 443.16,6734.1 h60
  text "PTH" at 1079.72,6734.1 h60
  text "Round" at 1338.86,6734.1 h60
  text "Top Layer - Bottom Layer" at 1714.02,6734.1 h60
  text "B" at -214.69,6724.1 h55.25
  text "8" at 111.16,6609.78 h60
  text "1.100mm (43.31mil)" at 443.16,6609.78 h60
  text "PTH" at 1079.72,6609.78 h60
  text "Round" at 1338.86,6609.78 h60
  text "Top Layer - Bottom Layer" at 1714.02,6609.78 h60
  text "12" at 111.16,6485.46 h60
  text "1.191mm (46.90mil)" at 443.16,6485.46 h60
  text "PTH" at 1079.72,6485.46 h60
  text "Round" at 1338.86,6485.46 h60
  text "Top Layer - Bottom Layer" at 1714.02,6485.46 h60
  text "E" at -214.69,6475.47 h55.25
  text "2" at 111.16,6361.14 h60
  text "1.350mm (53.15mil)" at 443.16,6361.14 h60
  text "PTH" at 1079.72,6361.14 h60
  text "Round" at 1338.86,6361.14 h60
  text "Top Layer - Bottom Layer" at 1714.02,6361.14 h60
  text "12" at 111.16,6236.82 h60
  text "1.575mm (62.00mil)" at 443.16,6236.82 h60
  text "PTH" at 1079.72,6236.82 h60
  text "Round" at 1338.86,6236.82 h60
  text "Top Layer - Bottom Layer" at 1714.02,6236.82 h60
  text "12" at 111.16,6112.5 h60
  text "1.600mm (62.99mil)" at 443.16,6112.5 h60
  text "PTH" at 1079.72,6112.5 h60
  text "Round" at 1338.86,6112.5 h60
  text "Top Layer - Bottom Layer" at 1714.02,6112.5 h60
  text "30" at 111.16,5988.18 h60
  text "1.700mm (66.93mil)" at 443.16,5988.18 h60
  text "PTH" at 1079.72,5988.18 h60
  text "Round" at 1338.86,5988.18 h60
  text "Top Layer - Bottom Layer" at 1714.02,5988.18 h60
  text "2" at 111.16,5863.86 h60
  text "1.778mm (70.00mil)" at 443.16,5863.86 h60
  text "PTH" at 1079.72,5863.86 h60
  text "Round" at 1338.86,5863.86 h60
  text "Top Layer - Bottom Layer" at 1714.02,5863.86 h60
  text "F" at -214.69,5853.86 h55.25
  text "2" at 111.16,5739.54 h60
  text "1.980mm (77.95mil)" at 443.16,5739.54 h60
  text "PTH" at 1079.72,5739.54 h60
  text "Round" at 1338.86,5739.54 h60
  text "Top Layer - Bottom Layer" at 1714.02,5739.54 h60
  text "A" at -214.69,5729.55 h55.25
  text "6" at 111.16,5615.22 h60
  text "2.000mm (78.74mil)" at 443.16,5615.22 h60
  text "PTH" at 1079.72,5615.22 h60
  text "Round" at 1338.86,5615.22 h60
  text "Top Layer - Bottom Layer" at 1714.02,5615.22 h60
  text "1" at 111.16,5490.9 h60
  text "2.060mm (81.10mil)" at 443.16,5490.9 h60
  text "PTH" at 1079.72,5490.9 h60
  text "Round" at 1338.86,5490.9 h60
  text "Top Layer - Bottom Layer" at 1714.02,5490.9 h60
  text "2" at 111.16,5366.58 h60
  text "2.540mm (100.00mil)" at 443.16,5366.58 h60
  text "PTH" at 1079.72,5366.58 h60
  text "Round" at 1338.86,5366.58 h60
  text "Top Layer - Bottom Layer" at 1714.02,5366.58 h60
  text "8" at 111.16,5242.26 h60
  text "2.600mm (102.36mil)" at 443.16,5242.26 h60
  text "PTH" at 1079.72,5242.26 h60
  text "Round" at 1338.86,5242.26 h60
  text "Top Layer - Bottom Layer" at 1714.02,5242.26 h60
  text "2" at 111.16,5117.94 h60
  text "3.200mm (126.00mil)" at 443.16,5117.94 h60
  text "PTH" at 1079.72,5117.94 h60
  text "Round" at 1338.86,5117.94 h60
  text "Top Layer - Bottom Layer" at 1714.02,5117.94 h60
  text "H" at -214.69,5107.94 h55.25
  text "465 Total" at 111.16,4993.62 h60
  text ".Layer_Name" at 577,-858.49 h60
M17 Embedded Cavity:
  text ".Layer_Name" at 577,-858.49 h60
M18 Embedded Assembly:
  text ".Layer_Name" at 577,-858.49 h60
M19 Embedded Keepout:
  text ".Layer_Name" at 577,-858.49 h60

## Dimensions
0,-400 to 1000,-400 on M2 Board Dimensions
